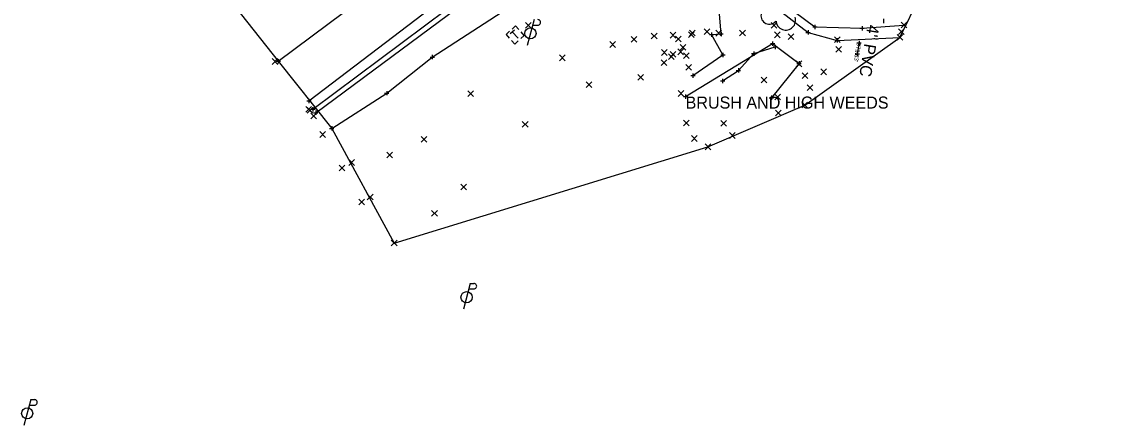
# Model space of a CAD drawing. Extents: x 120332 to 120776, y 463407 to 463745.
# Drawn here: x 120332.3 to 120583.4, y 463407.1 to 463500.9 of the extents above; entities that cross this region are included whole.
import ezdxf

# ---------------------------------------------------------------- set-up
doc = ezdxf.new("R2010")
doc.units = 0
for name, color, linetype in [('_CIVIL_CONSTRUCTION', 7, 'Continuous'), ('Default', 7, 'Continuous'), ('DR_X_Storm_Sewer', 7, 'Continuous'), ('DR_X_Text', 7, 'Continuous'), ('DV_X_Property_Line', 7, 'Continuous'), ('GE_X_Alignment', 7, 'Continuous'), ('GE_X_Alignment_100_Bearings', 7, 'Continuous'), ('GE_X_Alignment_100_Cardinal_Points', 7, 'Continuous'), ('GE_X_Alignment_100_Distances', 7, 'Continuous'), ('GE_X_Alignment_100_Stations', 7, 'Continuous'), ('RW_X_Esmt_SH', 7, 'Continuous'), ('SC_Scratch1', 7, 'Continuous'), ('SC_Scratch3', 7, 'Continuous'), ('SV_P_Control_Cells_Set', 7, 'Continuous'), ('SV_X_Break_Lines', 7, 'Continuous'), ('SV_X_Mon_Cells_Found', 7, 'Continuous'), ('SV_X_Terrain_Boundary', 7, 'Continuous'), ('VG_X_Tree_Line_Lt', 7, 'Continuous')]:
    doc.layers.add(name, color=color, linetype=linetype)

msp = doc.modelspace()

# ---------------------------------------------------------------- linework, layer by layer
at = {"layer": '_CIVIL_CONSTRUCTION'}
for centre, radius, start, end in [((120506.35, 463502.28), 1.97, 96.1722, 320.5737), ((120510.15, 463501.22), 2.28, 184.9476, 19.4572)]:
    msp.add_arc(centre, radius, start, end, dxfattribs=at)
at = {"layer": 'DR_X_Storm_Sewer'}
msp.add_line((120527.19, 463495.97), (120526.78, 463493.45), dxfattribs=at)
at = {"layer": 'DV_X_Property_Line'}
for p, q in [((120526.69, 463495.97), (120527.69, 463495.97)), ((120527.19, 463496.47), (120527.19, 463495.47)), ((120527.19, 463495.97), (120527.19, 463495.97)), ((120526.28, 463493.45), (120527.28, 463493.45)), ((120526.78, 463493.95), (120526.78, 463492.95)), ((120526.78, 463493.45), (120526.78, 463493.45))]:
    msp.add_line(p, q, dxfattribs=at)
at = {"layer": 'GE_X_Alignment'}
msp.add_lwpolyline([(120400.78, 463479.74), (120442.74, 463510.89), (120464.41, 463527.27), (120481.24, 463539.36), (120504.94, 463557.9), (120520.74, 463569.69), (120562.77, 463600.78)], dxfattribs=at)
at = {"layer": 'GE_X_Alignment_100_Bearings'}
msp.add_lwpolyline([(120400.11, 463480.54), (120441.64, 463511.61), (120463.87, 463528.17), (120480.16, 463540.69), (120504.52, 463558.73), (120520.21, 463570.42), (120561.99, 463601.9)], dxfattribs=at)
at = {"layer": 'GE_X_Alignment_100_Cardinal_Points'}
for points in [[(120392.05, 463491.7), (120434.29, 463523.26), (120458.68, 463541.48), (120471.62, 463551.86), (120496.01, 463569.76), (120511.36, 463581.53), (120553.61, 463612.98)], [(120399.18, 463482.46), (120440.01, 463513.66), (120462.57, 463530.32), (120478.53, 463542.4), (120503.14, 463560.74), (120518.65, 463572.53), (120560.39, 463604.03)]]:
    msp.add_lwpolyline(points, dxfattribs=at)
at = {"layer": 'GE_X_Alignment_100_Distances'}
msp.add_lwpolyline([(120392.05, 463491.7), (120434.29, 463523.26), (120458.68, 463541.48), (120471.62, 463551.86), (120496.01, 463569.76), (120511.36, 463581.53), (120553.61, 463612.98)], dxfattribs=at)
at = {"layer": 'GE_X_Alignment_100_Stations'}
msp.add_lwpolyline([(120399.18, 463482.46), (120440.01, 463513.66), (120462.57, 463530.32), (120478.53, 463542.4), (120503.14, 463560.74), (120518.65, 463572.53), (120560.39, 463604.03)], dxfattribs=at)
at = {"layer": 'RW_X_Esmt_SH'}
for p, q in [((120451.59, 463501.38), (120449.98, 463495.38)), ((120451.25, 463500.11), (120452.44, 463500.11)), ((120436.73, 463440.04), (120435.12, 463434.04)), ((120436.39, 463438.77), (120437.58, 463438.77)), ((120436.73, 463440.04), (120437.58, 463440.04)), ((120334.47, 463413.05), (120332.87, 463407.05)), ((120334.47, 463413.05), (120335.32, 463413.05)), ((120334.13, 463411.78), (120335.32, 463411.78))]:
    msp.add_line(p, q, dxfattribs=at)
for centre in [(120450.73, 463498.18), (120435.87, 463436.84), (120333.62, 463409.85)]:
    msp.add_circle(centre, 1.3, dxfattribs=at)
for centre in [(120452.45, 463500.74), (120437.59, 463439.41), (120335.33, 463412.41)]:
    msp.add_arc(centre, 0.638, 268.8767, 91.1233, dxfattribs=at)
at = {"layer": 'SC_Scratch3'}
for p, q in [((120446.03, 463498.11), (120446.99, 463498.98)), ((120447.86, 463497.07), (120446.51, 463498.55)), ((120447.18, 463497.81), (120447.18, 463497.81))]:
    msp.add_line(p, q, dxfattribs=at)
for points in [[(120445.88, 463498.65), (120445.07, 463497.91), (120445.8, 463497.09)], [(120448.03, 463499.11), (120447.29, 463499.93), (120446.47, 463499.19)], [(120448.49, 463496.96), (120449.3, 463497.7), (120448.56, 463498.52)], [(120446.34, 463496.5), (120447.08, 463495.69), (120447.9, 463496.43)]]:
    msp.add_lwpolyline(points, dxfattribs=at)
at = {"layer": 'SV_P_Control_Cells_Set'}
for p, q in [((120449.58, 463499.36), (120450.91, 463500.69)), ((120449.58, 463500.69), (120450.91, 463499.36)), ((120483.25, 463497.09), (120484.58, 463498.42)), ((120483.25, 463498.42), (120484.58, 463497.09)), ((120487.5, 463497.2), (120488.84, 463498.53)), ((120487.5, 463498.53), (120488.84, 463497.2)), ((120487.71, 463497.61), (120489.05, 463498.95)), ((120487.71, 463498.95), (120489.05, 463497.61)), ((120491.14, 463497.9), (120492.48, 463499.24)), ((120491.14, 463499.24), (120492.48, 463497.9)), ((120493.87, 463497.56), (120495.21, 463498.89)), ((120493.87, 463498.89), (120495.21, 463497.56)), ((120499.42, 463497.6), (120500.75, 463498.93)), ((120499.42, 463498.93), (120500.75, 463497.6)), ((120506.73, 463499.37), (120508.06, 463500.7)), ((120506.73, 463500.7), (120508.06, 463499.37)), ((120507.49, 463497.17), (120508.83, 463498.5)), ((120507.49, 463498.5), (120508.83, 463497.17)), ((120536.38, 463497.92), (120537.72, 463499.26)), ((120536.38, 463499.26), (120537.72, 463497.92)), ((120536.97, 463499.45), (120538.3, 463500.79)), ((120536.97, 463500.79), (120538.3, 463499.45)), ((120469.22, 463494.92), (120470.55, 463496.26)), ((120469.22, 463496.26), (120470.55, 463494.92)), ((120474.18, 463496.1), (120475.52, 463497.43)), ((120474.18, 463497.43), (120475.52, 463496.1)), ((120478.86, 463496.89), (120480.2, 463498.22)), ((120478.86, 463498.22), (120480.2, 463496.89)), ((120484.45, 463496.19), (120485.78, 463497.52)), ((120484.45, 463497.52), (120485.78, 463496.19)), ((120510.71, 463496.74), (120512.04, 463498.07)), ((120510.71, 463498.07), (120512.04, 463496.74)), ((120521.49, 463496.06), (120522.82, 463497.4)), ((120521.49, 463497.4), (120522.82, 463496.06)), ((120536.04, 463496.58), (120537.37, 463497.91)), ((120536.04, 463497.91), (120537.37, 463496.58)), ((120481.24, 463493.06), (120482.58, 463494.39)), ((120481.24, 463494.39), (120482.58, 463493.06)), ((120482.86, 463492.09), (120484.2, 463493.43)), ((120482.86, 463493.43), (120484.2, 463492.09)), ((120483.22, 463492.64), (120484.55, 463493.97)), ((120483.22, 463493.97), (120484.55, 463492.64)), ((120485.03, 463493.21), (120486.37, 463494.55)), ((120485.03, 463494.55), (120486.37, 463493.21)), ((120485.59, 463494.29), (120486.92, 463495.62)), ((120485.59, 463495.62), (120486.92, 463494.29)), ((120486.32, 463492.35), (120487.65, 463493.69)), ((120486.32, 463493.69), (120487.65, 463492.35)), ((120521.79, 463493.78), (120523.13, 463495.11)), ((120521.79, 463495.11), (120523.13, 463493.78)), ((120390.61, 463490.97), (120391.94, 463492.31)), ((120390.61, 463492.31), (120391.94, 463490.97)), ((120457.47, 463491.83), (120458.81, 463493.17)), ((120457.47, 463493.17), (120458.81, 463491.83)), ((120481.12, 463490.72), (120482.45, 463492.06)), ((120481.12, 463492.06), (120482.45, 463490.72)), ((120486.92, 463489.59), (120488.25, 463490.92)), ((120486.92, 463490.92), (120488.25, 463489.59)), ((120512.59, 463490.43), (120513.92, 463491.76)), ((120512.59, 463491.76), (120513.92, 463490.43)), ((120475.74, 463487.31), (120477.08, 463488.64)), ((120475.74, 463488.64), (120477.08, 463487.31)), ((120513.96, 463487.69), (120515.3, 463489.02)), ((120513.96, 463489.02), (120515.3, 463487.69)), ((120518.28, 463488.56), (120519.61, 463489.9)), ((120518.28, 463489.9), (120519.61, 463488.56)), ((120463.69, 463485.56), (120465.02, 463486.89)), ((120463.69, 463486.89), (120465.02, 463485.56)), ((120504.4, 463486.65), (120505.73, 463487.98)), ((120504.4, 463487.98), (120505.73, 463486.65)), ((120515.15, 463484.92), (120516.48, 463486.25)), ((120515.15, 463486.25), (120516.48, 463484.92)), ((120436.18, 463483.5), (120437.51, 463484.83)), ((120436.18, 463484.83), (120437.51, 463483.5)), ((120485.08, 463483.53), (120486.42, 463484.87)), ((120485.08, 463484.87), (120486.42, 463483.53)), ((120507.63, 463482.75), (120508.96, 463484.08)), ((120507.63, 463484.08), (120508.96, 463482.75)), ((120398.46, 463479.83), (120399.79, 463481.16)), ((120398.46, 463481.16), (120399.79, 463479.83)), ((120398.75, 463479.59), (120400.08, 463480.92)), ((120398.75, 463480.92), (120400.08, 463479.59)), ((120513.9, 463480.83), (120515.23, 463482.16)), ((120513.9, 463482.16), (120515.23, 463480.83)), ((120399.6, 463478.32), (120400.94, 463479.66)), ((120399.6, 463479.66), (120400.94, 463478.32)), ((120507.77, 463479.02), (120509.1, 463480.35)), ((120507.77, 463480.35), (120509.1, 463479.02)), ((120448.83, 463476.34), (120450.17, 463477.67)), ((120448.83, 463477.67), (120450.17, 463476.34)), ((120486.34, 463476.65), (120487.67, 463477.99)), ((120486.34, 463477.99), (120487.67, 463476.65)), ((120495.04, 463476.6), (120496.37, 463477.94)), ((120495.04, 463477.94), (120496.37, 463476.6)), ((120401.73, 463474.01), (120403.06, 463475.35)), ((120401.73, 463475.35), (120403.06, 463474.01)), ((120425.32, 463472.87), (120426.65, 463474.21)), ((120425.32, 463474.21), (120426.65, 463472.87)), ((120488.18, 463473.07), (120489.51, 463474.4)), ((120488.18, 463474.4), (120489.51, 463473.07)), ((120497.03, 463473.76), (120498.37, 463475.1)), ((120497.03, 463475.1), (120498.37, 463473.76)), ((120491.39, 463471.14), (120492.72, 463472.48)), ((120491.39, 463472.48), (120492.72, 463471.14)), ((120408.46, 463467.49), (120409.79, 463468.83)), ((120408.46, 463468.83), (120409.79, 463467.49)), ((120417.3, 463469.23), (120418.64, 463470.57)), ((120417.3, 463470.57), (120418.64, 463469.23)), ((120406.21, 463466.23), (120407.54, 463467.57)), ((120406.21, 463467.57), (120407.54, 463466.23)), ((120412.76, 463459.47), (120414.1, 463460.81)), ((120412.76, 463460.81), (120414.1, 463459.47)), ((120434.54, 463461.77), (120435.87, 463463.1)), ((120434.54, 463463.1), (120435.87, 463461.77)), ((120410.77, 463458.29), (120412.1, 463459.62)), ((120410.77, 463459.62), (120412.1, 463458.29)), ((120427.73, 463455.69), (120429.07, 463457.03)), ((120427.73, 463457.03), (120429.07, 463455.69)), ((120418.34, 463448.77), (120419.68, 463450.11)), ((120418.34, 463450.11), (120419.68, 463448.77))]:
    msp.add_line(p, q, dxfattribs=at)
at = {"layer": 'SV_X_Break_Lines'}
for points in [[(120404.48, 463476.09), (120417.28, 463484.28), (120427.88, 463492.66), (120446.76, 463504.9), (120457.39, 463511.51), (120460.21, 463513.58), (120464.33, 463516.37), (120471.69, 463517.42), (120474.18, 463519.5), (120472.87, 463523.16), (120471.44, 463528.25), (120473.17, 463531.08), (120477.51, 463533.67), (120480.81, 463534.7), (120483.38, 463533.34), (120485.99, 463535.41), (120486.75, 463538.23), (120491.56, 463542.13), (120495.7, 463547.27)], [(120493.02, 463511.75), (120507.64, 463506.68), (120516.93, 463499.67), (120527.89, 463499.38), (120537.63, 463500.12)], [(120488.53, 463488.37), (120495.53, 463493.15), (120492.87, 463497.88), (120495.09, 463498.05), (120494.52, 463505.44), (120496.73, 463508.35), (120498.86, 463507.09), (120503.51, 463506.36), (120508.21, 463503.91), (120515.35, 463498.4), (120522.14, 463496.55), (120536.71, 463497.24)], [(120495.44, 463487.13), (120499.14, 463489.56), (120502.68, 463493.47), (120507.69, 463495.03)]]:
    msp.add_lwpolyline(points, dxfattribs=at)
at = {"layer": 'SV_X_Mon_Cells_Found'}
for p, q in [((120532.86, 463501.57), (120532.86, 463500.57)), ((120492.87, 463498.38), (120492.87, 463497.38)), ((120495.09, 463498.55), (120495.09, 463497.55)), ((120514.85, 463498.4), (120515.85, 463498.4)), ((120515.35, 463498.9), (120515.35, 463497.9)), ((120515.35, 463498.4), (120515.35, 463498.4)), ((120516.43, 463499.67), (120517.43, 463499.67)), ((120516.93, 463500.17), (120516.93, 463499.17)), ((120516.93, 463499.67), (120516.93, 463499.67)), ((120527.39, 463499.38), (120528.39, 463499.38)), ((120527.89, 463499.88), (120527.89, 463498.88)), ((120527.89, 463499.38), (120527.89, 463499.38)), ((120492.37, 463497.88), (120493.37, 463497.88)), ((120492.87, 463497.88), (120492.87, 463497.88)), ((120494.59, 463498.05), (120495.59, 463498.05)), ((120495.09, 463498.05), (120495.09, 463498.05)), ((120506.58, 463495.79), (120507.58, 463495.79)), ((120507.08, 463496.29), (120507.08, 463495.29)), ((120507.08, 463495.79), (120507.08, 463495.79)), ((120521.64, 463496.55), (120522.64, 463496.55)), ((120522.14, 463497.05), (120522.14, 463496.05)), ((120522.14, 463496.55), (120522.14, 463496.55)), ((120495.53, 463493.65), (120495.53, 463492.65)), ((120502.18, 463493.47), (120503.18, 463493.47)), ((120502.68, 463493.97), (120502.68, 463492.97)), ((120502.68, 463493.47), (120502.68, 463493.47)), ((120507.19, 463495.03), (120508.19, 463495.03)), ((120507.69, 463495.53), (120507.69, 463494.53)), ((120507.69, 463495.03), (120507.69, 463495.03)), ((120391.55, 463491.7), (120392.55, 463491.7)), ((120391.55, 463491.7), (120392.55, 463491.7)), ((120392.05, 463492.2), (120392.05, 463491.2)), ((120392.05, 463492.2), (120392.05, 463491.2)), ((120392.05, 463491.7), (120392.05, 463491.7)), ((120392.05, 463491.7), (120392.05, 463491.7)), ((120427.38, 463492.66), (120428.38, 463492.66)), ((120427.88, 463493.16), (120427.88, 463492.16)), ((120427.88, 463492.66), (120427.88, 463492.66)), ((120495.03, 463493.15), (120496.03, 463493.15)), ((120495.53, 463493.15), (120495.53, 463493.15)), ((120512.74, 463491.19), (120513.74, 463491.19)), ((120513.24, 463491.69), (120513.24, 463490.69)), ((120513.24, 463491.19), (120513.24, 463491.19)), ((120488.03, 463488.37), (120489.03, 463488.37)), ((120488.53, 463488.87), (120488.53, 463487.87)), ((120488.53, 463488.37), (120488.53, 463488.37)), ((120498.64, 463489.56), (120499.64, 463489.56)), ((120499.14, 463490.06), (120499.14, 463489.06)), ((120499.14, 463489.56), (120499.14, 463489.56)), ((120494.94, 463487.13), (120495.94, 463487.13)), ((120495.44, 463487.63), (120495.44, 463486.63)), ((120495.44, 463487.13), (120495.44, 463487.13)), ((120416.78, 463484.28), (120417.78, 463484.28)), ((120417.28, 463484.78), (120417.28, 463483.78)), ((120417.28, 463484.28), (120417.28, 463484.28)), ((120486.34, 463483.49), (120487.34, 463483.49)), ((120486.84, 463483.99), (120486.84, 463482.99)), ((120486.84, 463483.49), (120486.84, 463483.49)), ((120506.81, 463483.71), (120506.81, 463482.71)), ((120398.68, 463482.46), (120399.68, 463482.46)), ((120398.68, 463482.46), (120399.68, 463482.46)), ((120399.18, 463482.96), (120399.18, 463481.96)), ((120399.18, 463482.96), (120399.18, 463481.96)), ((120399.18, 463482.46), (120399.18, 463482.46)), ((120399.18, 463482.46), (120399.18, 463482.46)), ((120400.11, 463481.04), (120400.11, 463480.04)), ((120506.31, 463483.21), (120507.31, 463483.21)), ((120506.81, 463483.21), (120506.81, 463483.21)), ((120399.61, 463480.54), (120400.61, 463480.54)), ((120400.11, 463480.54), (120400.11, 463480.54)), ((120400.28, 463479.74), (120401.28, 463479.74)), ((120400.78, 463480.24), (120400.78, 463479.24)), ((120400.78, 463479.74), (120400.78, 463479.74)), ((120403.98, 463476.09), (120404.98, 463476.09)), ((120404.48, 463476.59), (120404.48, 463475.59)), ((120404.48, 463476.09), (120404.48, 463476.09))]:
    msp.add_line(p, q, dxfattribs=at)
at = {"layer": 'SV_X_Terrain_Boundary'}
msp.add_lwpolyline([(120382.05, 463504.31), (120392.05, 463491.7), (120404.48, 463476.09), (120419.01, 463449.44), (120492.05, 463471.81), (120514.57, 463481.5), (120536.71, 463497.24), (120541.46, 463506.92), (120568.63, 463561.6), (120583.37, 463575.39), (120540.78, 463632.41), (120527.21, 463655.25), (120435.5, 463626.86), (120399.02, 463601.89), (120359.63, 463534.8), (120382.05, 463504.31)], dxfattribs=at)
at = {"layer": 'VG_X_Tree_Line_Lt'}
msp.add_lwpolyline([(120486.84, 463483.49), (120507.08, 463495.79), (120513.24, 463491.19), (120506.81, 463483.21)], dxfattribs=at)

# ---------------------------------------------------------------- texts
at = {"layer": 'Default'}
msp.add_text('BRUSH AND HIGH WEEDS', height=2.8, dxfattribs=at).set_placement((120486.84, 463480.69))
at = {"layer": 'DR_X_Text'}
msp.add_text('4" PVC', height=2.8, rotation=260.7283, dxfattribs=at).set_placement((120529.19, 463500.32))
at = {"layer": 'SC_Scratch1'}
msp.add_text("971.83'", height=1, rotation=260.7283, dxfattribs=at).set_placement((120526.7, 463496.05))

doc.saveas('drawing.dxf')
